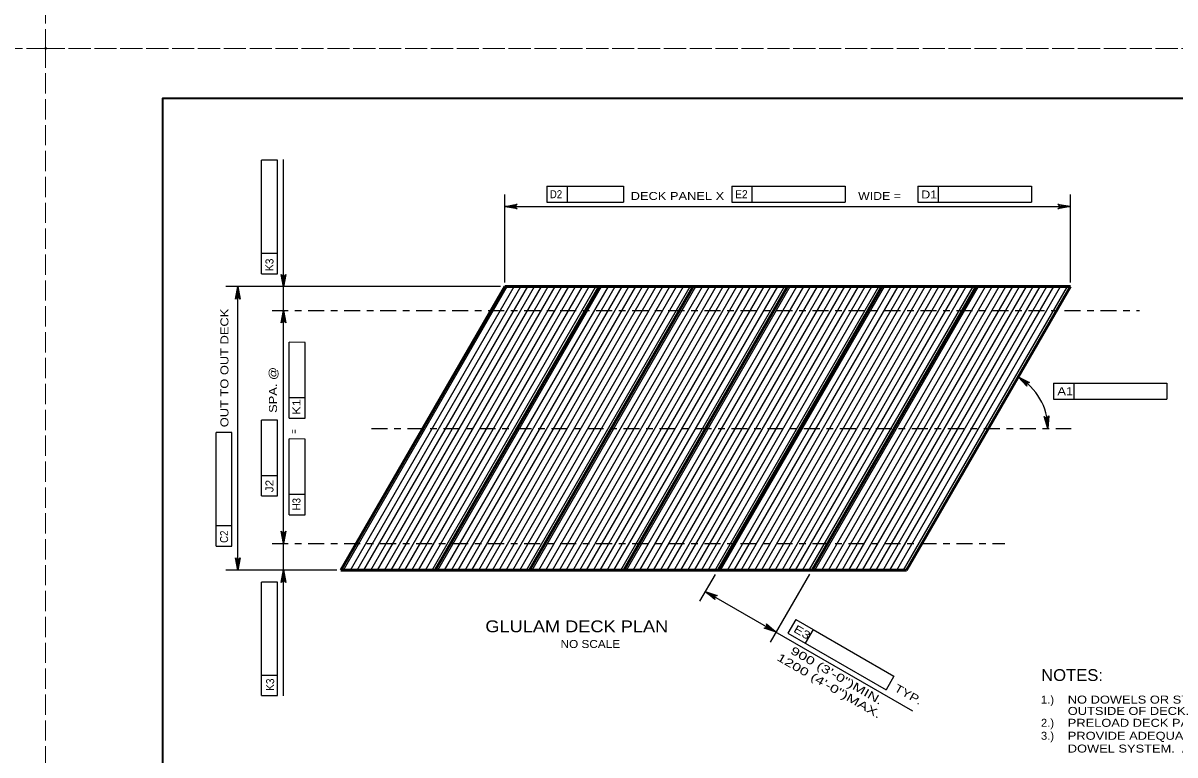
# Model space of a CAD drawing. Extents: x -11 to 79, y -154 to 0.
# Drawn here: x 33.66 to 50.93, y -76.59 to -65.62 of the extents above; entities that cross this region are included whole.
import ezdxf
from ezdxf.enums import TextEntityAlignment as Align

# ---------------------------------------------------------------- set-up
doc = ezdxf.new("R2010")
doc.units = 0
doc.header["$LTSCALE"] = 0.048
doc.header["$PDMODE"] = 32
doc.header["$PDSIZE"] = 0.024
doc.linetypes.add('DOT_DASHED', pattern=[7.7, 5, -1.2, 0.3, -1.2])
doc.linetypes.add('LONG_DASHED', pattern=[7.5, 6, -1.5])
for name, color, linetype, lineweight in [('1', 7, 'Continuous', 25), ('2', 7, 'Continuous', 35), ('4', 7, 'Continuous', 25), ('5', 7, 'Continuous', 25), ('63', 7, 'LONG_DASHED', 13)]:
    doc.layers.add(name, color=color, linetype=linetype, lineweight=lineweight)
doc.layers.add('62', color=7, linetype='Continuous')

msp = doc.modelspace()

# ---------------------------------------------------------------- linework, layer by layer
at = {"layer": '1', "lineweight": 35}
msp.add_lwpolyline([(35.75, -87.25), (67.25, -87.25), (67.25, -66.75), (35.75, -66.75)], close=True, dxfattribs=at)
at = {"layer": '2', "lineweight": 53}
for p, q in [((38.42783, -73.8225), (40.88267, -69.5705)), ((39.84092, -73.8225), (42.29583, -69.5705)), ((40.88267, -69.5705), (49.36142, -69.5705)), ((41.25408, -73.8225), (43.70892, -69.5705)), ((42.66717, -73.8225), (45.12208, -69.5705)), ((44.08033, -73.8225), (46.53517, -69.5705)), ((45.49342, -73.8225), (47.94833, -69.5705)), ((46.90658, -73.8225), (49.36142, -69.5705)), ((46.90658, -73.8225), (38.42783, -73.8225))]:
    msp.add_line(p, q, dxfattribs=at)
at = {"layer": '4'}
for p, q in [((37.47433, -67.6765), (37.23808, -67.67625)), ((37.23808, -69.07458), (37.23808, -67.67625)), ((37.47433, -69.37733), (37.47433, -67.6765)), ((37.56642, -75.70575), (37.56642, -67.66692)), ((40.88267, -69.508), (40.88267, -68.19142)), ((41.51467, -68.06642), (41.81708, -68.06642)), ((41.51467, -68.06642), (41.51467, -68.30267)), ((41.81708, -68.06642), (41.81708, -68.30267)), ((41.81708, -68.06642), (42.66125, -68.06642)), ((42.66125, -68.06642), (42.66125, -68.30267)), ((44.2855, -68.06642), (44.58792, -68.06642)), ((44.2855, -68.06642), (44.2855, -68.30267)), ((44.58792, -68.06642), (44.58792, -68.30267)), ((44.58792, -68.06642), (45.98625, -68.06642)), ((45.98625, -68.06642), (45.98625, -68.30267)), ((47.07683, -68.06642), (47.07683, -68.30267)), ((47.07683, -68.06642), (47.37933, -68.06642)), ((47.37933, -68.06642), (47.37933, -68.30267)), ((47.37933, -68.06642), (48.77767, -68.06642)), ((48.77767, -68.06642), (48.77767, -68.30267)), ((49.36142, -69.508), (49.36142, -68.19142)), ((40.88267, -68.37142), (49.36142, -68.37142)), ((41.51467, -68.30267), (42.66125, -68.30267)), ((44.2855, -68.30267), (45.98625, -68.30267)), ((47.07683, -68.30267), (48.77767, -68.30267)), ((37.23808, -69.37708), (37.23808, -69.07458)), ((37.47433, -69.07483), (37.23808, -69.07458)), ((37.23808, -69.37708), (37.47433, -69.37733)), ((40.82017, -69.5705), (36.6995, -69.5705)), ((36.8795, -73.8225), (36.8795, -69.5705)), ((37.88867, -70.40542), (37.6525, -70.40517)), ((37.6525, -71.24542), (37.6525, -70.40517)), ((37.88867, -71.54158), (37.88867, -70.40542)), ((49.10883, -71.0195), (49.10883, -71.25567)), ((49.41125, -71.0195), (50.80958, -71.0195)), ((50.80958, -71.0195), (50.80958, -71.25567)), ((37.88867, -71.23917), (37.6525, -71.23892)), ((37.6525, -71.54133), (37.6525, -71.24542)), ((49.10883, -71.25567), (50.80958, -71.25567)), ((37.47433, -71.57225), (37.23808, -71.572)), ((37.23808, -72.40575), (37.23808, -71.572)), ((37.47433, -72.70842), (37.47433, -71.57225)), ((37.6525, -71.54133), (37.88867, -71.54158)), ((36.79375, -71.75942), (36.5575, -71.75917)), ((36.5575, -73.1575), (36.5575, -71.75917)), ((36.79375, -73.46017), (36.79375, -71.75942)), ((37.88867, -71.8545), (37.6525, -71.85425)), ((37.6525, -72.688), (37.6525, -71.85425)), ((37.88867, -72.99075), (37.88867, -71.8545)), ((37.23808, -72.70817), (37.23808, -72.40575)), ((37.47433, -72.406), (37.23808, -72.40575)), ((37.6525, -72.9905), (37.6525, -72.688)), ((37.88867, -72.68825), (37.6525, -72.688)), ((37.23808, -72.70817), (37.47433, -72.70842)), ((37.6525, -72.9905), (37.88867, -72.99075)), ((36.5575, -73.45992), (36.5575, -73.1575)), ((36.79375, -73.15775), (36.5575, -73.1575)), ((36.5575, -73.45992), (36.79375, -73.46017)), ((38.36533, -73.8225), (36.6995, -73.8225)), ((44.037, -73.88325), (43.80442, -74.28592)), ((45.45092, -73.88233), (44.86408, -74.89808)), ((37.47433, -74), (37.23808, -73.99975)), ((37.23808, -75.39808), (37.23808, -73.99975)), ((37.47433, -75.70083), (37.47433, -74)), ((46.99833, -75.93467), (43.8895, -74.13858)), ((45.2445, -74.55858), (45.12633, -74.76317)), ((45.12633, -74.76317), (46.599, -75.61392)), ((45.50642, -74.70992), (46.71717, -75.40942)), ((37.23808, -75.7005), (37.23808, -75.39808)), ((37.47433, -75.39833), (37.23808, -75.39808)), ((46.71717, -75.40942), (46.599, -75.61392)), ((37.23808, -75.7005), (37.47433, -75.70083))]:
    msp.add_line(p, q, dxfattribs=at)
at = {"layer": '4', "linetype": 'DOT_DASHED'}
for p, q in [((37.395, -69.92917), (50.39567, -69.92917)), ((38.88392, -71.6965), (49.37533, -71.6965)), ((37.395, -73.42017), (48.38017, -73.42017))]:
    msp.add_line(p, q, dxfattribs=at)
at = {"layer": '4'}
for points in [[(40.88267, -68.37142), (41.06908, -68.3365), (41.05475, -68.34642), (41.04733, -68.35892), (41.04517, -68.37142), (41.04733, -68.38392), (41.05475, -68.39642), (41.06908, -68.40633), (40.88267, -68.37142), (41.05475, -68.39642), (41.04733, -68.38392), (40.88267, -68.37142), (41.04517, -68.37142), (41.04733, -68.35892), (40.88267, -68.37142), (41.05475, -68.34642)], [(49.36142, -68.37142), (49.175, -68.40633), (49.18933, -68.39642), (49.19675, -68.38392), (49.19892, -68.37142), (49.19675, -68.35892), (49.18933, -68.34642), (49.175, -68.3365), (49.36142, -68.37142), (49.18933, -68.34642), (49.19675, -68.35892), (49.36142, -68.37142), (49.19892, -68.37142), (49.19675, -68.38392), (49.36142, -68.37142), (49.18933, -68.39642)], [(37.56642, -69.57525), (37.5315, -69.38883), (37.54142, -69.40317), (37.55392, -69.41058), (37.56642, -69.41275), (37.57892, -69.41058), (37.59142, -69.40317), (37.60133, -69.38883), (37.56642, -69.57525), (37.59142, -69.40317), (37.57892, -69.41058), (37.56642, -69.57525), (37.56642, -69.41275), (37.55392, -69.41058), (37.56642, -69.57525), (37.54142, -69.40317)], [(36.8795, -69.5705), (36.91442, -69.75692), (36.9045, -69.74258), (36.892, -69.73517), (36.8795, -69.733), (36.867, -69.73517), (36.8545, -69.74258), (36.84458, -69.75692), (36.8795, -69.5705), (36.8545, -69.74258), (36.867, -69.73517), (36.8795, -69.5705), (36.8795, -69.733), (36.892, -69.73517), (36.8795, -69.5705), (36.9045, -69.74258)], [(37.56642, -69.92917), (37.60133, -70.1155), (37.59142, -70.10117), (37.57892, -70.09375), (37.56642, -70.09167), (37.55392, -70.09375), (37.54142, -70.10117), (37.5315, -70.1155), (37.56642, -69.92917), (37.54142, -70.10117), (37.55392, -70.09375), (37.56642, -69.92917), (37.56642, -70.09167), (37.57892, -70.09375), (37.56642, -69.92917), (37.59142, -70.10117)], [(48.58, -70.92417), (48.75117, -71.00575), (48.73367, -71.00542), (48.72033, -71.01108), (48.71117, -71.01992), (48.70558, -71.03133), (48.70425, -71.04575), (48.70992, -71.06225), (48.58, -70.92417), (48.70425, -71.04575), (48.70558, -71.03133), (48.58, -70.92417), (48.71117, -71.01992), (48.72033, -71.01108), (48.58, -70.92417), (48.73367, -71.00542)], [(49.10883, -71.0195), (49.41125, -71.0195), (49.41125, -71.25567)], [(49.02517, -71.69742), (48.96733, -71.51683), (48.97892, -71.52983), (48.99225, -71.53558), (49.00492, -71.53617), (49.01708, -71.5325), (49.02858, -71.52358), (49.03667, -71.50808), (49.02517, -71.69742), (49.02858, -71.52358), (49.01708, -71.5325), (49.02517, -71.69742), (49.00492, -71.53617), (48.99225, -71.53558), (49.02517, -71.69742), (48.97892, -71.52983)], [(37.56642, -73.42017), (37.5315, -73.23375), (37.54142, -73.24808), (37.55392, -73.2555), (37.56642, -73.25767), (37.57892, -73.2555), (37.59142, -73.24808), (37.60133, -73.23375), (37.56642, -73.42017), (37.59142, -73.24808), (37.57892, -73.2555), (37.56642, -73.42017), (37.56642, -73.25767), (37.55392, -73.2555), (37.56642, -73.42017), (37.54142, -73.24808)], [(36.8795, -73.8225), (36.84458, -73.63608), (36.8545, -73.65042), (36.867, -73.65783), (36.8795, -73.66), (36.892, -73.65783), (36.9045, -73.65042), (36.91442, -73.63608), (36.8795, -73.8225), (36.9045, -73.65042), (36.892, -73.65783), (36.8795, -73.8225), (36.8795, -73.66), (36.867, -73.65783), (36.8795, -73.8225), (36.8545, -73.65042)], [(37.56642, -73.818), (37.60133, -74.00442), (37.59142, -73.99008), (37.57892, -73.98267), (37.56642, -73.9805), (37.55392, -73.98267), (37.54142, -73.99008), (37.5315, -74.00442), (37.56642, -73.818), (37.54142, -73.99008), (37.55392, -73.98267), (37.56642, -73.818), (37.56642, -73.9805), (37.57892, -73.98267), (37.56642, -73.818), (37.59142, -73.99008)], [(43.8895, -74.13858), (44.06842, -74.20158), (44.051, -74.203), (44.03833, -74.21008), (44.03017, -74.21983), (44.02583, -74.23175), (44.026, -74.24633), (44.03342, -74.26208), (43.8895, -74.13858), (44.026, -74.24633), (44.02583, -74.23175), (43.8895, -74.13858), (44.03017, -74.21983), (44.03833, -74.21008), (43.8895, -74.13858), (44.051, -74.203)], [(45.2445, -74.55858), (45.50642, -74.70992), (45.38825, -74.91442)], [(44.94917, -74.75083), (44.77025, -74.68783), (44.78767, -74.68642), (44.80033, -74.67925), (44.8085, -74.6695), (44.81283, -74.65758), (44.81267, -74.64308), (44.80525, -74.62725), (44.94917, -74.75083), (44.81267, -74.64308), (44.81283, -74.65758), (44.94917, -74.75083), (44.8085, -74.6695), (44.80033, -74.67925), (44.94917, -74.75083), (44.78767, -74.68642)]]:
    msp.add_lwpolyline(points, dxfattribs=at)
msp.add_arc((48.13398, -71.69649), 0.89111, 359.99937, 60.00065, dxfattribs=at)
at = {"layer": '5'}
for p, q in [((38.46617, -73.8225), (40.921, -69.5705)), ((38.56842, -73.8225), (41.02325, -69.5705)), ((38.67067, -73.8225), (41.12558, -69.5705)), ((38.773, -73.8225), (41.22783, -69.5705)), ((38.87525, -73.8225), (41.33017, -69.5705)), ((38.97758, -73.8225), (41.43242, -69.5705)), ((39.07983, -73.8225), (41.53475, -69.5705)), ((39.18217, -73.8225), (41.637, -69.5705)), ((39.28442, -73.8225), (41.73925, -69.5705)), ((39.38667, -73.8225), (41.84158, -69.5705)), ((39.489, -73.8225), (41.94383, -69.5705)), ((39.59125, -73.8225), (42.04617, -69.5705)), ((39.69358, -73.8225), (42.14842, -69.5705)), ((39.79583, -73.8225), (42.25075, -69.5705)), ((39.87925, -73.8225), (42.33408, -69.5705)), ((39.9815, -73.8225), (42.43642, -69.5705)), ((40.08383, -73.8225), (42.53867, -69.5705)), ((40.18608, -73.8225), (42.641, -69.5705)), ((40.28842, -73.8225), (42.74325, -69.5705)), ((40.39067, -73.8225), (42.84558, -69.5705)), ((40.493, -73.8225), (42.94783, -69.5705)), ((40.59525, -73.8225), (43.05017, -69.5705)), ((40.69758, -73.8225), (43.15242, -69.5705)), ((40.79983, -73.8225), (43.25467, -69.5705)), ((40.90208, -73.8225), (43.357, -69.5705)), ((41.00442, -73.8225), (43.45925, -69.5705)), ((41.10667, -73.8225), (43.56158, -69.5705)), ((41.209, -73.8225), (43.66383, -69.5705)), ((41.29242, -73.8225), (43.74725, -69.5705)), ((41.39467, -73.8225), (43.8495, -69.5705)), ((41.49692, -73.8225), (43.95183, -69.5705)), ((41.59925, -73.8225), (44.05408, -69.5705)), ((41.7015, -73.8225), (44.15642, -69.5705)), ((41.80383, -73.8225), (44.25867, -69.5705)), ((41.90608, -73.8225), (44.361, -69.5705)), ((42.00842, -73.8225), (44.46325, -69.5705)), ((42.11067, -73.8225), (44.5655, -69.5705)), ((42.21292, -73.8225), (44.66783, -69.5705)), ((42.31525, -73.8225), (44.77008, -69.5705)), ((42.4175, -73.8225), (44.87242, -69.5705)), ((42.51983, -73.8225), (44.97467, -69.5705)), ((42.62208, -73.8225), (45.077, -69.5705)), ((42.7055, -73.8225), (45.16033, -69.5705)), ((42.80775, -73.8225), (45.26267, -69.5705)), ((42.91008, -73.8225), (45.36492, -69.5705)), ((43.01233, -73.8225), (45.46725, -69.5705)), ((43.11467, -73.8225), (45.5695, -69.5705)), ((43.21692, -73.8225), (45.67183, -69.5705)), ((43.31925, -73.8225), (45.77408, -69.5705)), ((43.4215, -73.8225), (45.87642, -69.5705)), ((43.52383, -73.8225), (45.97867, -69.5705)), ((43.62608, -73.8225), (46.08092, -69.5705)), ((43.72833, -73.8225), (46.18325, -69.5705)), ((43.83067, -73.8225), (46.2855, -69.5705)), ((43.93292, -73.8225), (46.38783, -69.5705)), ((44.03525, -73.8225), (46.49008, -69.5705)), ((44.11867, -73.8225), (46.5735, -69.5705)), ((44.22092, -73.8225), (46.67575, -69.5705)), ((44.32317, -73.8225), (46.77808, -69.5705)), ((44.4255, -73.8225), (46.88033, -69.5705)), ((44.52775, -73.8225), (46.98267, -69.5705)), ((44.63008, -73.8225), (47.08492, -69.5705)), ((44.73233, -73.8225), (47.18725, -69.5705)), ((44.83467, -73.8225), (47.2895, -69.5705)), ((44.93692, -73.8225), (47.39175, -69.5705)), ((45.03917, -73.8225), (47.49408, -69.5705)), ((45.1415, -73.8225), (47.59633, -69.5705)), ((45.24375, -73.8225), (47.69867, -69.5705)), ((45.34608, -73.8225), (47.80092, -69.5705)), ((45.44833, -73.8225), (47.90325, -69.5705)), ((45.53175, -73.8225), (47.98658, -69.5705)), ((45.63408, -73.8225), (48.08892, -69.5705)), ((45.73633, -73.8225), (48.19117, -69.5705)), ((45.83858, -73.8225), (48.2935, -69.5705)), ((45.94092, -73.8225), (48.39575, -69.5705)), ((46.04317, -73.8225), (48.49808, -69.5705)), ((46.1455, -73.8225), (48.60033, -69.5705)), ((46.24775, -73.8225), (48.70267, -69.5705)), ((46.35008, -73.8225), (48.80492, -69.5705)), ((46.45233, -73.8225), (48.90717, -69.5705)), ((46.55458, -73.8225), (49.0095, -69.5705)), ((46.65692, -73.8225), (49.11175, -69.5705)), ((46.75917, -73.8225), (49.21408, -69.5705)), ((46.8615, -73.8225), (49.31633, -69.5705))]:
    msp.add_line(p, q, dxfattribs=at)
at = {"layer": '62'}
msp.add_point((34, -66), dxfattribs=at)
at = {"layer": '63'}
for points in [[(0, -66), (34, -66), (34, -44), (0, -44)], [(34, -66), (68, -66), (68, -44), (34, -44)], [(0, -88), (34, -88), (34, -66), (0, -66)], [(34, -88), (68, -88), (68, -66), (34, -66)]]:
    msp.add_lwpolyline(points, close=True, dxfattribs=at)

# ---------------------------------------------------------------- texts
at = {"layer": '4'}
for s, rotation, width, p in [('D2', 359.938, 0.9, (41.65102, -68.2446)), ('E2', 359.938, 0.95, (44.4301, -68.2446)), ('D1', 359.938, 1.15, (47.2456, -68.24913)), ('K3', 89.938, 0.95, (37.41618, -69.24315)), ('OUT TO OUT DECK', 90, 1.2, (36.74083, -70.78975)), ('A1', 359.938, 1.2, (49.28502, -71.19763)), ('K1', 89.938, 1.2, (37.82096, -71.37423)), ('J2', 89.938, 1.1, (37.41627, -72.5594)), ('H3', 89.938, 0.9, (37.82093, -72.83156)), ('C2', 89.938, 0.9, (36.73568, -73.31973)), ('E3', 329.923, 1.3, (45.31114, -74.80286)), ('1200 (4\'-0")MAX.', 329.979, 1.45, (45.71619, -75.60532)), ('900 (3\'-0")MIN.', 329.979, 1.45, (45.83015, -75.45195)), ('K3', 89.938, 0.95, (37.42577, -75.53765))]:
    msp.add_text(s, height=0.12, rotation=rotation, dxfattribs=dict(at, width=width)).set_placement(p, align=Align.CENTER)
for s, height, width, p in [('DECK PANEL X', 0.12, 1.2, (42.77042, -68.27142)), ('WIDE =', 0.12, 1.15, (46.18058, -68.27142)), ('NO SCALE', 0.12, 1.1, (41.71933, -74.9875)), ('NOTES:', 0.1772, 1.05, (48.924, -75.48175)), ('1.)', 0.12, 1.05, (48.92058, -75.821)), ('NO DOWELS OR STIFFENER BEAMS NEEDED BETWEEN FACIA BEAM AND ', 0.12, 1.2, (49.32283, -75.821)), ('OUTSIDE OF DECK.', 0.12, 1.2, (49.32283, -75.991)), ('2.)', 0.12, 1.05, (48.92058, -76.16908)), ('PRELOAD DECK PANEL WHILE FASTENING PANEL TO BEAM.', 0.12, 1.2, (49.32283, -76.16908)), ('3.)', 0.12, 1.05, (48.92058, -76.363)), ('PROVIDE ADEQUATE SPACING BETWEEN THE DECK ANCHORAGE AND THE ', 0.12, 1.2, (49.32283, -76.363)), ('DOWEL SYSTEM.  ADJUSTMENTS TO THE DOWEL SYSTEM AND/OR DECK', 0.12, 1.2, (49.32283, -76.55492))]:
    msp.add_text(s, height=height, dxfattribs=dict(at, width=width)).set_placement(p)
for s, rotation, width, p in [('SPA. @', 90, 1.2, (37.46833, -71.46258)), ('=', 90, 0.6, (37.77742, -71.77325)), ('TYP.', 330.587, 1.25, (46.71125, -75.62567))]:
    msp.add_text(s, height=0.12, rotation=rotation, dxfattribs=dict(at, width=width)).set_placement(p)
at = {"layer": '4', "width": 1.15}
msp.add_text('GLULAM DECK PLAN', height=0.1772, dxfattribs=at).set_placement((41.96275, -74.75133), align=Align.CENTER)

doc.saveas('drawing.dxf')
